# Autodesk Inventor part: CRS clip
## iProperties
Author: Rich
Shininess: 20.0
PropertySet Name: _Private Model Information
Created: 2001-04
Part Number: CRS clip
Document SubType Name: Modeling
Designer: Rich
Control State: 0
Master: False
Checked Out: False
PropertySet Name: Design Tracking Control
Density: 0.0
Volumn: 0.0
Area: 0.0
PropertySet Name: Model Information
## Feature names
1. Extrusion2
2. Extrusion3
3. Hole1
